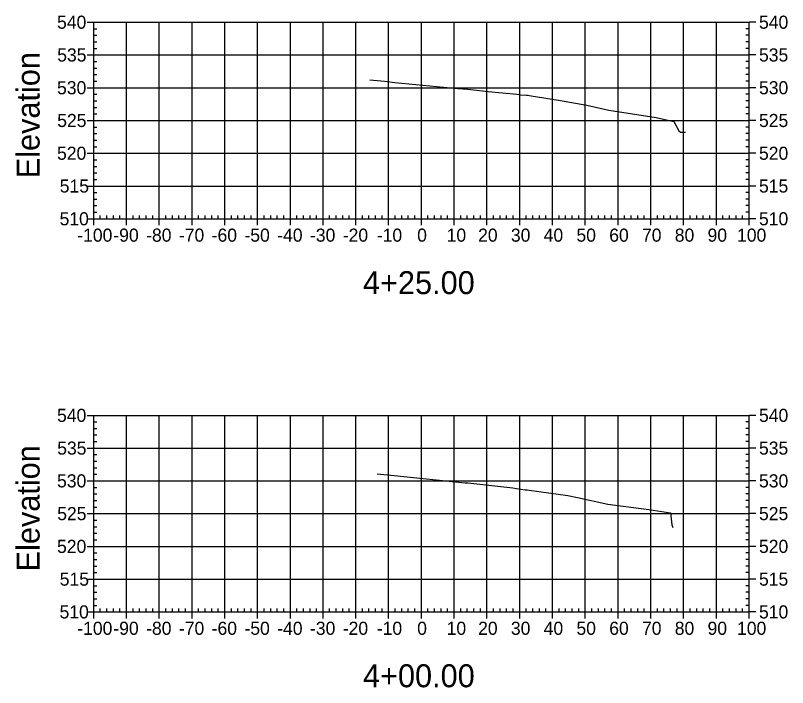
# Model space of a CAD drawing. Extents: x 708103 to 717568, y 374476 to 378707.
# Drawn here: x 715957.6 to 716193.2, y 376765 to 376970.1 of the extents above; entities that cross this region are included whole.
import ezdxf

# ---------------------------------------------------------------- set-up
doc = ezdxf.new("R2010")
doc.units = 0
for name, color, linetype in [('1', 7, 'Continuous'), ('57', 7, 'Continuous'), ('60', 7, 'Continuous'), ('Existing', 7, 'Continuous')]:
    doc.layers.add(name, color=color, linetype=linetype)

msp = doc.modelspace()

# ---------------------------------------------------------------- linework, layer by layer
at = {"layer": '57'}
for p, q in [((715979.5, 376968.07), (715981.5, 376968.07)), ((715981.5, 376968.07), (716181.5, 376968.07)), ((715981.5, 376908.07), (715981.5, 376968.07)), ((715981.5, 376908.07), (715981.5, 376968.07)), ((715991.5, 376908.07), (715991.5, 376968.07)), ((716001.5, 376908.07), (716001.5, 376968.07)), ((716011.5, 376908.07), (716011.5, 376968.07)), ((716021.5, 376908.07), (716021.5, 376968.07)), ((716031.5, 376908.07), (716031.5, 376968.07)), ((716041.5, 376908.07), (716041.5, 376968.07)), ((716051.5, 376908.07), (716051.5, 376968.07)), ((716061.5, 376908.07), (716061.5, 376968.07)), ((716071.5, 376908.07), (716071.5, 376968.07)), ((716081.5, 376908.07), (716081.5, 376968.07)), ((716091.5, 376908.07), (716091.5, 376968.07)), ((716101.5, 376908.07), (716101.5, 376968.07)), ((716111.5, 376908.07), (716111.5, 376968.07)), ((716121.5, 376908.07), (716121.5, 376968.07)), ((716131.5, 376908.07), (716131.5, 376968.07)), ((716141.5, 376908.07), (716141.5, 376968.07)), ((716151.5, 376908.07), (716151.5, 376968.07)), ((716161.5, 376908.07), (716161.5, 376968.07)), ((716171.5, 376908.07), (716171.5, 376968.07)), ((716181.5, 376908.07), (716181.5, 376968.07)), ((716181.5, 376908.07), (716181.5, 376968.07)), ((716183.5, 376968.07), (716181.5, 376968.07)), ((715981.5, 376966.07), (715982.5, 376966.07)), ((716181.5, 376966.07), (716180.5, 376966.07)), ((715981.5, 376964.07), (715982.5, 376964.07)), ((716181.5, 376964.07), (716180.5, 376964.07)), ((715981.5, 376962.07), (715982.5, 376962.07)), ((715981.5, 376960.07), (715982.5, 376960.07)), ((716181.5, 376962.07), (716180.5, 376962.07)), ((716181.5, 376960.07), (716180.5, 376960.07)), ((715979.5, 376958.07), (715981.5, 376958.07)), ((715981.5, 376958.07), (716181.5, 376958.07)), ((716183.5, 376958.07), (716181.5, 376958.07)), ((715981.5, 376956.07), (715982.5, 376956.07)), ((716181.5, 376956.07), (716180.5, 376956.07)), ((715981.5, 376954.07), (715982.5, 376954.07)), ((716181.5, 376954.07), (716180.5, 376954.07)), ((715981.5, 376952.07), (715982.5, 376952.07)), ((716181.5, 376952.07), (716180.5, 376952.07)), ((715979.5, 376948.07), (715981.5, 376948.07)), ((715981.5, 376950.07), (715982.5, 376950.07)), ((715981.5, 376948.07), (716181.5, 376948.07)), ((716181.5, 376950.07), (716180.5, 376950.07)), ((716183.5, 376948.07), (716181.5, 376948.07)), ((715981.5, 376946.07), (715982.5, 376946.07)), ((716181.5, 376946.07), (716180.5, 376946.07)), ((715981.5, 376944.07), (715982.5, 376944.07)), ((716181.5, 376944.07), (716180.5, 376944.07)), ((715981.5, 376942.07), (715982.5, 376942.07)), ((716181.5, 376942.07), (716180.5, 376942.07)), ((715981.5, 376940.07), (715982.5, 376940.07)), ((716181.5, 376940.07), (716180.5, 376940.07)), ((715979.5, 376938.07), (715981.5, 376938.07)), ((715981.5, 376938.07), (716181.5, 376938.07)), ((716183.5, 376938.07), (716181.5, 376938.07)), ((715981.5, 376936.07), (715982.5, 376936.07)), ((715981.5, 376934.07), (715982.5, 376934.07)), ((716181.5, 376936.07), (716180.5, 376936.07)), ((716181.5, 376934.07), (716180.5, 376934.07)), ((715981.5, 376932.07), (715982.5, 376932.07)), ((716181.5, 376932.07), (716180.5, 376932.07)), ((715981.5, 376930.07), (715982.5, 376930.07)), ((716181.5, 376930.07), (716180.5, 376930.07)), ((715979.5, 376928.07), (715981.5, 376928.07)), ((715981.5, 376928.07), (716181.5, 376928.07)), ((716183.5, 376928.07), (716181.5, 376928.07)), ((715981.5, 376926.07), (715982.5, 376926.07)), ((716181.5, 376926.07), (716180.5, 376926.07)), ((715981.5, 376924.07), (715982.5, 376924.07)), ((716181.5, 376924.07), (716180.5, 376924.07)), ((715981.5, 376922.07), (715982.5, 376922.07)), ((715981.5, 376920.07), (715982.5, 376920.07)), ((716181.5, 376922.07), (716180.5, 376922.07)), ((716181.5, 376920.07), (716180.5, 376920.07)), ((715979.5, 376918.07), (715981.5, 376918.07)), ((715981.5, 376918.07), (716181.5, 376918.07)), ((716183.5, 376918.07), (716181.5, 376918.07)), ((715981.5, 376916.07), (715982.5, 376916.07)), ((716181.5, 376916.07), (716180.5, 376916.07)), ((715981.5, 376914.07), (715982.5, 376914.07)), ((716181.5, 376914.07), (716180.5, 376914.07)), ((715981.5, 376912.07), (715982.5, 376912.07)), ((716181.5, 376912.07), (716180.5, 376912.07)), ((715979.5, 376908.07), (715981.5, 376908.07)), ((715981.5, 376910.07), (715982.5, 376910.07)), ((715981.5, 376908.07), (716181.5, 376908.07)), ((715981.5, 376908.07), (716181.5, 376908.07)), ((715981.5, 376906.07), (715981.5, 376908.07)), ((715983.5, 376908.07), (715983.5, 376909.07)), ((715985.5, 376908.07), (715985.5, 376909.07)), ((715987.5, 376908.07), (715987.5, 376909.07)), ((715989.5, 376908.07), (715989.5, 376909.07)), ((715991.5, 376906.07), (715991.5, 376908.07)), ((715993.5, 376908.07), (715993.5, 376909.07)), ((715995.5, 376908.07), (715995.5, 376909.07)), ((715997.5, 376908.07), (715997.5, 376909.07)), ((715999.5, 376908.07), (715999.5, 376909.07)), ((716001.5, 376906.07), (716001.5, 376908.07)), ((716003.5, 376908.07), (716003.5, 376909.07)), ((716005.5, 376908.07), (716005.5, 376909.07)), ((716007.5, 376908.07), (716007.5, 376909.07)), ((716009.5, 376908.07), (716009.5, 376909.07)), ((716011.5, 376906.07), (716011.5, 376908.07)), ((716013.5, 376908.07), (716013.5, 376909.07)), ((716015.5, 376908.07), (716015.5, 376909.07)), ((716017.5, 376908.07), (716017.5, 376909.07)), ((716019.5, 376908.07), (716019.5, 376909.07)), ((716021.5, 376906.07), (716021.5, 376908.07)), ((716023.5, 376908.07), (716023.5, 376909.07)), ((716025.5, 376908.07), (716025.5, 376909.07)), ((716027.5, 376908.07), (716027.5, 376909.07)), ((716029.5, 376908.07), (716029.5, 376909.07)), ((716031.5, 376906.07), (716031.5, 376908.07)), ((716033.5, 376908.07), (716033.5, 376909.07)), ((716035.5, 376908.07), (716035.5, 376909.07)), ((716037.5, 376908.07), (716037.5, 376909.07)), ((716039.5, 376908.07), (716039.5, 376909.07)), ((716041.5, 376906.07), (716041.5, 376908.07)), ((716043.5, 376908.07), (716043.5, 376909.07)), ((716045.5, 376908.07), (716045.5, 376909.07)), ((716047.5, 376908.07), (716047.5, 376909.07)), ((716049.5, 376908.07), (716049.5, 376909.07)), ((716051.5, 376906.07), (716051.5, 376908.07)), ((716053.5, 376908.07), (716053.5, 376909.07)), ((716055.5, 376908.07), (716055.5, 376909.07)), ((716057.5, 376908.07), (716057.5, 376909.07)), ((716059.5, 376908.07), (716059.5, 376909.07)), ((716061.5, 376906.07), (716061.5, 376908.07)), ((716063.5, 376908.07), (716063.5, 376909.07)), ((716065.5, 376908.07), (716065.5, 376909.07)), ((716067.5, 376908.07), (716067.5, 376909.07)), ((716069.5, 376908.07), (716069.5, 376909.07)), ((716071.5, 376906.07), (716071.5, 376908.07)), ((716073.5, 376908.07), (716073.5, 376909.07)), ((716075.5, 376908.07), (716075.5, 376909.07)), ((716077.5, 376908.07), (716077.5, 376909.07)), ((716079.5, 376908.07), (716079.5, 376909.07)), ((716081.5, 376906.07), (716081.5, 376908.07)), ((716083.5, 376908.07), (716083.5, 376909.07)), ((716085.5, 376908.07), (716085.5, 376909.07)), ((716087.5, 376908.07), (716087.5, 376909.07)), ((716089.5, 376908.07), (716089.5, 376909.07)), ((716091.5, 376906.07), (716091.5, 376908.07)), ((716093.5, 376908.07), (716093.5, 376909.07)), ((716095.5, 376908.07), (716095.5, 376909.07)), ((716097.5, 376908.07), (716097.5, 376909.07)), ((716099.5, 376908.07), (716099.5, 376909.07)), ((716101.5, 376906.07), (716101.5, 376908.07)), ((716103.5, 376908.07), (716103.5, 376909.07)), ((716105.5, 376908.07), (716105.5, 376909.07)), ((716107.5, 376908.07), (716107.5, 376909.07)), ((716109.5, 376908.07), (716109.5, 376909.07)), ((716111.5, 376906.07), (716111.5, 376908.07)), ((716113.5, 376908.07), (716113.5, 376909.07)), ((716115.5, 376908.07), (716115.5, 376909.07)), ((716117.5, 376908.07), (716117.5, 376909.07)), ((716119.5, 376908.07), (716119.5, 376909.07)), ((716121.5, 376906.07), (716121.5, 376908.07)), ((716123.5, 376908.07), (716123.5, 376909.07)), ((716125.5, 376908.07), (716125.5, 376909.07)), ((716127.5, 376908.07), (716127.5, 376909.07)), ((716129.5, 376908.07), (716129.5, 376909.07)), ((716131.5, 376906.07), (716131.5, 376908.07)), ((716133.5, 376908.07), (716133.5, 376909.07)), ((716135.5, 376908.07), (716135.5, 376909.07)), ((716137.5, 376908.07), (716137.5, 376909.07)), ((716139.5, 376908.07), (716139.5, 376909.07)), ((716141.5, 376906.07), (716141.5, 376908.07)), ((716143.5, 376908.07), (716143.5, 376909.07)), ((716145.5, 376908.07), (716145.5, 376909.07)), ((716147.5, 376908.07), (716147.5, 376909.07)), ((716149.5, 376908.07), (716149.5, 376909.07)), ((716151.5, 376906.07), (716151.5, 376908.07)), ((716153.5, 376908.07), (716153.5, 376909.07)), ((716155.5, 376908.07), (716155.5, 376909.07)), ((716157.5, 376908.07), (716157.5, 376909.07)), ((716159.5, 376908.07), (716159.5, 376909.07)), ((716161.5, 376906.07), (716161.5, 376908.07)), ((716163.5, 376908.07), (716163.5, 376909.07)), ((716165.5, 376908.07), (716165.5, 376909.07)), ((716167.5, 376908.07), (716167.5, 376909.07)), ((716169.5, 376908.07), (716169.5, 376909.07)), ((716171.5, 376906.07), (716171.5, 376908.07)), ((716173.5, 376908.07), (716173.5, 376909.07)), ((716175.5, 376908.07), (716175.5, 376909.07)), ((716177.5, 376908.07), (716177.5, 376909.07)), ((716179.5, 376908.07), (716179.5, 376909.07)), ((716181.5, 376910.07), (716180.5, 376910.07)), ((716181.5, 376906.07), (716181.5, 376908.07)), ((716183.5, 376908.07), (716181.5, 376908.07)), ((715979.5, 376848.07), (715981.5, 376848.07)), ((715981.5, 376848.07), (716181.5, 376848.07)), ((715981.5, 376788.07), (715981.5, 376848.07)), ((715981.5, 376788.07), (715981.5, 376848.07)), ((715991.5, 376788.07), (715991.5, 376848.07)), ((716001.5, 376788.07), (716001.5, 376848.07)), ((716011.5, 376788.07), (716011.5, 376848.07)), ((716021.5, 376788.07), (716021.5, 376848.07)), ((716031.5, 376788.07), (716031.5, 376848.07)), ((716041.5, 376788.07), (716041.5, 376848.07)), ((716051.5, 376788.07), (716051.5, 376848.07)), ((716061.5, 376788.07), (716061.5, 376848.07)), ((716071.5, 376788.07), (716071.5, 376848.07)), ((716081.5, 376788.07), (716081.5, 376848.07)), ((716091.5, 376788.07), (716091.5, 376848.07)), ((716101.5, 376788.07), (716101.5, 376848.07)), ((716111.5, 376788.07), (716111.5, 376848.07)), ((716121.5, 376788.07), (716121.5, 376848.07)), ((716131.5, 376788.07), (716131.5, 376848.07)), ((716141.5, 376788.07), (716141.5, 376848.07)), ((716151.5, 376788.07), (716151.5, 376848.07)), ((716161.5, 376788.07), (716161.5, 376848.07)), ((716171.5, 376788.07), (716171.5, 376848.07)), ((716181.5, 376788.07), (716181.5, 376848.07)), ((716181.5, 376788.07), (716181.5, 376848.07)), ((716183.5, 376848.07), (716181.5, 376848.07)), ((715981.5, 376846.07), (715982.5, 376846.07)), ((716181.5, 376846.07), (716180.5, 376846.07)), ((715981.5, 376844.07), (715982.5, 376844.07)), ((715981.5, 376842.07), (715982.5, 376842.07)), ((716181.5, 376844.07), (716180.5, 376844.07)), ((716181.5, 376842.07), (716180.5, 376842.07)), ((715981.5, 376840.07), (715982.5, 376840.07)), ((716181.5, 376840.07), (716180.5, 376840.07)), ((715979.5, 376838.07), (715981.5, 376838.07)), ((715981.5, 376838.07), (716181.5, 376838.07)), ((716183.5, 376838.07), (716181.5, 376838.07)), ((715981.5, 376836.07), (715982.5, 376836.07)), ((716181.5, 376836.07), (716180.5, 376836.07)), ((715981.5, 376834.07), (715982.5, 376834.07)), ((716181.5, 376834.07), (716180.5, 376834.07)), ((715981.5, 376832.07), (715982.5, 376832.07)), ((716181.5, 376832.07), (716180.5, 376832.07)), ((715979.5, 376828.07), (715981.5, 376828.07)), ((715981.5, 376830.07), (715982.5, 376830.07)), ((715981.5, 376828.07), (716181.5, 376828.07)), ((716181.5, 376830.07), (716180.5, 376830.07)), ((716183.5, 376828.07), (716181.5, 376828.07)), ((715981.5, 376826.07), (715982.5, 376826.07)), ((716181.5, 376826.07), (716180.5, 376826.07)), ((715981.5, 376824.07), (715982.5, 376824.07)), ((716181.5, 376824.07), (716180.5, 376824.07)), ((715981.5, 376822.07), (715982.5, 376822.07)), ((716181.5, 376822.07), (716180.5, 376822.07)), ((715981.5, 376820.07), (715982.5, 376820.07)), ((716181.5, 376820.07), (716180.5, 376820.07)), ((715979.5, 376818.07), (715981.5, 376818.07)), ((715981.5, 376818.07), (716181.5, 376818.07)), ((716183.5, 376818.07), (716181.5, 376818.07)), ((715981.5, 376816.07), (715982.5, 376816.07)), ((715981.5, 376814.07), (715982.5, 376814.07)), ((716181.5, 376816.07), (716180.5, 376816.07)), ((716181.5, 376814.07), (716180.5, 376814.07)), ((715981.5, 376812.07), (715982.5, 376812.07)), ((716181.5, 376812.07), (716180.5, 376812.07)), ((715981.5, 376810.07), (715982.5, 376810.07)), ((716181.5, 376810.07), (716180.5, 376810.07)), ((715979.5, 376808.07), (715981.5, 376808.07)), ((715981.5, 376808.07), (716181.5, 376808.07)), ((716183.5, 376808.07), (716181.5, 376808.07)), ((715981.5, 376806.07), (715982.5, 376806.07)), ((716181.5, 376806.07), (716180.5, 376806.07)), ((715981.5, 376804.07), (715982.5, 376804.07)), ((715981.5, 376802.07), (715982.5, 376802.07)), ((716181.5, 376804.07), (716180.5, 376804.07)), ((716181.5, 376802.07), (716180.5, 376802.07)), ((715981.5, 376800.07), (715982.5, 376800.07)), ((716181.5, 376800.07), (716180.5, 376800.07)), ((715979.5, 376798.07), (715981.5, 376798.07)), ((715981.5, 376798.07), (716181.5, 376798.07)), ((716183.5, 376798.07), (716181.5, 376798.07)), ((715981.5, 376796.07), (715982.5, 376796.07)), ((716181.5, 376796.07), (716180.5, 376796.07)), ((715981.5, 376794.07), (715982.5, 376794.07)), ((716181.5, 376794.07), (716180.5, 376794.07)), ((715981.5, 376792.07), (715982.5, 376792.07)), ((716181.5, 376792.07), (716180.5, 376792.07)), ((715979.5, 376788.07), (715981.5, 376788.07)), ((715981.5, 376790.07), (715982.5, 376790.07)), ((715981.5, 376788.07), (716181.5, 376788.07)), ((715981.5, 376788.07), (716181.5, 376788.07)), ((715981.5, 376786.07), (715981.5, 376788.07)), ((715983.5, 376788.07), (715983.5, 376789.07)), ((715985.5, 376788.07), (715985.5, 376789.07)), ((715987.5, 376788.07), (715987.5, 376789.07)), ((715989.5, 376788.07), (715989.5, 376789.07)), ((715991.5, 376786.07), (715991.5, 376788.07)), ((715993.5, 376788.07), (715993.5, 376789.07)), ((715995.5, 376788.07), (715995.5, 376789.07)), ((715997.5, 376788.07), (715997.5, 376789.07)), ((715999.5, 376788.07), (715999.5, 376789.07)), ((716001.5, 376786.07), (716001.5, 376788.07)), ((716003.5, 376788.07), (716003.5, 376789.07)), ((716005.5, 376788.07), (716005.5, 376789.07)), ((716007.5, 376788.07), (716007.5, 376789.07)), ((716009.5, 376788.07), (716009.5, 376789.07)), ((716011.5, 376786.07), (716011.5, 376788.07)), ((716013.5, 376788.07), (716013.5, 376789.07)), ((716015.5, 376788.07), (716015.5, 376789.07)), ((716017.5, 376788.07), (716017.5, 376789.07)), ((716019.5, 376788.07), (716019.5, 376789.07)), ((716021.5, 376786.07), (716021.5, 376788.07)), ((716023.5, 376788.07), (716023.5, 376789.07)), ((716025.5, 376788.07), (716025.5, 376789.07)), ((716027.5, 376788.07), (716027.5, 376789.07)), ((716029.5, 376788.07), (716029.5, 376789.07)), ((716031.5, 376786.07), (716031.5, 376788.07)), ((716033.5, 376788.07), (716033.5, 376789.07)), ((716035.5, 376788.07), (716035.5, 376789.07)), ((716037.5, 376788.07), (716037.5, 376789.07)), ((716039.5, 376788.07), (716039.5, 376789.07)), ((716041.5, 376786.07), (716041.5, 376788.07)), ((716043.5, 376788.07), (716043.5, 376789.07)), ((716045.5, 376788.07), (716045.5, 376789.07)), ((716047.5, 376788.07), (716047.5, 376789.07)), ((716049.5, 376788.07), (716049.5, 376789.07)), ((716051.5, 376786.07), (716051.5, 376788.07)), ((716053.5, 376788.07), (716053.5, 376789.07)), ((716055.5, 376788.07), (716055.5, 376789.07)), ((716057.5, 376788.07), (716057.5, 376789.07)), ((716059.5, 376788.07), (716059.5, 376789.07)), ((716061.5, 376786.07), (716061.5, 376788.07)), ((716063.5, 376788.07), (716063.5, 376789.07)), ((716065.5, 376788.07), (716065.5, 376789.07)), ((716067.5, 376788.07), (716067.5, 376789.07)), ((716069.5, 376788.07), (716069.5, 376789.07)), ((716071.5, 376786.07), (716071.5, 376788.07)), ((716073.5, 376788.07), (716073.5, 376789.07)), ((716075.5, 376788.07), (716075.5, 376789.07)), ((716077.5, 376788.07), (716077.5, 376789.07)), ((716079.5, 376788.07), (716079.5, 376789.07)), ((716081.5, 376786.07), (716081.5, 376788.07)), ((716083.5, 376788.07), (716083.5, 376789.07)), ((716085.5, 376788.07), (716085.5, 376789.07)), ((716087.5, 376788.07), (716087.5, 376789.07)), ((716089.5, 376788.07), (716089.5, 376789.07)), ((716091.5, 376786.07), (716091.5, 376788.07)), ((716093.5, 376788.07), (716093.5, 376789.07)), ((716095.5, 376788.07), (716095.5, 376789.07)), ((716097.5, 376788.07), (716097.5, 376789.07)), ((716099.5, 376788.07), (716099.5, 376789.07)), ((716101.5, 376786.07), (716101.5, 376788.07)), ((716103.5, 376788.07), (716103.5, 376789.07)), ((716105.5, 376788.07), (716105.5, 376789.07)), ((716107.5, 376788.07), (716107.5, 376789.07)), ((716109.5, 376788.07), (716109.5, 376789.07)), ((716111.5, 376786.07), (716111.5, 376788.07)), ((716113.5, 376788.07), (716113.5, 376789.07)), ((716115.5, 376788.07), (716115.5, 376789.07)), ((716117.5, 376788.07), (716117.5, 376789.07)), ((716119.5, 376788.07), (716119.5, 376789.07)), ((716121.5, 376786.07), (716121.5, 376788.07)), ((716123.5, 376788.07), (716123.5, 376789.07)), ((716125.5, 376788.07), (716125.5, 376789.07)), ((716127.5, 376788.07), (716127.5, 376789.07)), ((716129.5, 376788.07), (716129.5, 376789.07)), ((716131.5, 376786.07), (716131.5, 376788.07)), ((716133.5, 376788.07), (716133.5, 376789.07)), ((716135.5, 376788.07), (716135.5, 376789.07)), ((716137.5, 376788.07), (716137.5, 376789.07)), ((716139.5, 376788.07), (716139.5, 376789.07)), ((716141.5, 376786.07), (716141.5, 376788.07)), ((716143.5, 376788.07), (716143.5, 376789.07)), ((716145.5, 376788.07), (716145.5, 376789.07)), ((716147.5, 376788.07), (716147.5, 376789.07)), ((716149.5, 376788.07), (716149.5, 376789.07)), ((716151.5, 376786.07), (716151.5, 376788.07)), ((716153.5, 376788.07), (716153.5, 376789.07)), ((716155.5, 376788.07), (716155.5, 376789.07)), ((716157.5, 376788.07), (716157.5, 376789.07)), ((716159.5, 376788.07), (716159.5, 376789.07)), ((716161.5, 376786.07), (716161.5, 376788.07)), ((716163.5, 376788.07), (716163.5, 376789.07)), ((716165.5, 376788.07), (716165.5, 376789.07)), ((716167.5, 376788.07), (716167.5, 376789.07)), ((716169.5, 376788.07), (716169.5, 376789.07)), ((716171.5, 376786.07), (716171.5, 376788.07)), ((716173.5, 376788.07), (716173.5, 376789.07)), ((716175.5, 376788.07), (716175.5, 376789.07)), ((716177.5, 376788.07), (716177.5, 376789.07)), ((716179.5, 376788.07), (716179.5, 376789.07)), ((716181.5, 376790.07), (716180.5, 376790.07)), ((716181.5, 376786.07), (716181.5, 376788.07)), ((716183.5, 376788.07), (716181.5, 376788.07))]:
    msp.add_line(p, q, dxfattribs=at)
at = {"layer": 'Existing'}
for points in [[(716065.72, 376950.49), (716070.25, 376950.05), (716073.35, 376949.62), (716092.65, 376947.82), (716095.62, 376947.58), (716101.87, 376946.93), (716110.63, 376946.09), (716111.21, 376945.98), (716111.52, 376945.94), (716111.77, 376945.92), (716113.52, 376945.84), (716113.85, 376945.82), (716113.87, 376945.81), (716115.01, 376945.55), (716123.34, 376944.24), (716131.93, 376942.7), (716138.73, 376941.25), (716153.08, 376938.93), (716158.5, 376937.71), (716160, 376934.93), (716160.58, 376934.52), (716162.09, 376934.49)], [(716067.99, 376830.23), (716073.19, 376829.71), (716094.8, 376827.5), (716095.38, 376827.44), (716095.67, 376827.42), (716109.41, 376825.95), (716110.54, 376825.74), (716111.78, 376825.57), (716113.18, 376825.37), (716113.73, 376825.3), (716114.38, 376825.19), (716126.2, 376823.55), (716129.1, 376823.02), (716138.37, 376820.96), (716150.85, 376819.29), (716157.49, 376818.27), (716157.9, 376814.65), (716158.21, 376813.87)]]:
    msp.add_lwpolyline(points, dxfattribs=at)

# ---------------------------------------------------------------- texts
at = {"layer": '1'}
for s, p in [('4+25.00', (716063.67, 376885.07)), ('4+00.00', (716063.67, 376765.07))]:
    msp.add_text(s, height=7, dxfattribs=at).set_placement(p)
at = {"layer": '57'}
for s, p in [('540', (715970.32, 376966.07)), ('540', (716184.5, 376966.07)), ('535', (715970.37, 376956.07)), ('535', (716184.5, 376956.07)), ('530', (715970.32, 376946.07)), ('530', (716184.5, 376946.07)), ('525', (715970.37, 376936.07)), ('525', (716184.5, 376936.07)), ('520', (715970.32, 376926.07)), ('520', (716184.5, 376926.07)), ('515', (715971.14, 376916.07)), ('515', (716184.5, 376916.07)), ('510', (715971.09, 376906.07)), ('510', (716184.5, 376906.07)), ('-100', (715976.49, 376901.07)), ('-90', (715987.5, 376901.07)), ('-80', (715997.5, 376901.07)), ('-70', (716007.5, 376901.07)), ('-60', (716017.5, 376901.07)), ('-50', (716027.5, 376901.07)), ('-40', (716037.5, 376901.07)), ('-30', (716047.5, 376901.07)), ('-20', (716057.5, 376901.07)), ('-10', (716067.88, 376901.07)), ('0', (716080.2, 376901.07)), ('10', (716089.19, 376901.07)), ('20', (716098.8, 376901.07)), ('30', (716108.8, 376901.07)), ('40', (716118.8, 376901.07)), ('50', (716128.8, 376901.07)), ('60', (716138.8, 376901.07)), ('70', (716148.8, 376901.07)), ('80', (716158.8, 376901.07)), ('90', (716168.8, 376901.07)), ('100', (716177.8, 376901.07)), ('540', (715970.32, 376846.07)), ('540', (716184.5, 376846.07)), ('535', (715970.37, 376836.07)), ('535', (716184.5, 376836.07)), ('530', (715970.32, 376826.07)), ('530', (716184.5, 376826.07)), ('525', (715970.37, 376816.07)), ('525', (716184.5, 376816.07)), ('520', (715970.32, 376806.07)), ('520', (716184.5, 376806.07)), ('515', (715971.14, 376796.07)), ('515', (716184.5, 376796.07)), ('510', (715971.09, 376786.07)), ('510', (716184.5, 376786.07)), ('-100', (715976.49, 376781.07)), ('-90', (715987.5, 376781.07)), ('-80', (715997.5, 376781.07)), ('-70', (716007.5, 376781.07)), ('-60', (716017.5, 376781.07)), ('-50', (716027.5, 376781.07)), ('-40', (716037.5, 376781.07)), ('-30', (716047.5, 376781.07)), ('-20', (716057.5, 376781.07)), ('-10', (716067.88, 376781.07)), ('0', (716080.2, 376781.07)), ('10', (716089.19, 376781.07)), ('20', (716098.8, 376781.07)), ('30', (716108.8, 376781.07)), ('40', (716118.8, 376781.07)), ('50', (716128.8, 376781.07)), ('60', (716138.8, 376781.07)), ('70', (716148.8, 376781.07)), ('80', (716158.8, 376781.07)), ('90', (716168.8, 376781.07)), ('100', (716177.8, 376781.07))]:
    msp.add_text(s, height=4, dxfattribs=at).set_placement(p)
at = {"layer": '60'}
for p in [(715965, 376920.44), (715965, 376800.44)]:
    msp.add_text('Elevation', height=7, rotation=90, dxfattribs=at).set_placement(p)

doc.saveas('drawing.dxf')
